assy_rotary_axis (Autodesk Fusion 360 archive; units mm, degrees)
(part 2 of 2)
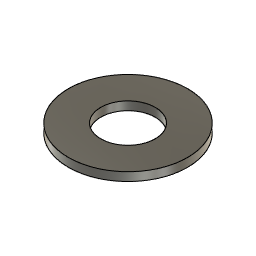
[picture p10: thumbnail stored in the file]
sketch "Sketch1" plane through (0, 0, 0) normal (0, 1, 0) x axis (1, 0, 0)
  line L1 (3.5, 0) -> (1.6, 0)
  line L2 (3.5, -0.5) -> (3.5, 0)
  line L3 (1.6, -0.5) -> (3.5, -0.5)
  line L4 (1.6, 0) -> (1.6, -0.5)
  point P1 (0, 0)
  point P2 (1.6, 0)
  point P5 (1.6, -0.5)
  horizontal L1
  vertical L2
  horizontal L3
  vertical L4
  coincident P1 L1
  dimension "d1" distance P2 P5 = 0.5
  dimension "d2" distance P1 L4 = 1.6 (= "( 3.2 / 2 ) * 1 mm")
  dimension "d3" distance P1 L2 = 3.5 (= "( 7 / 2 ) * 1 mm")
revolve "Revolve1" sketch "Sketch1" AlongAngle 360

design "PP_TRNS_GT2-Pulley-20T-6mm"
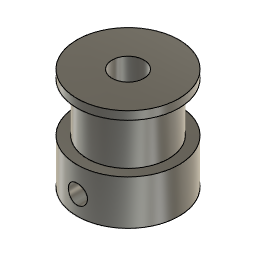
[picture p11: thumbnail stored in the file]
sketch "Sketch1" plane through (0, 0, 0) normal (0, 1, 0) x axis (1, 0, 0)
  line L1 (8, 0) -> (0, 0)
  line L2 (8, -7) -> (8, 0)
  line L3 (6.3662, -7) -> (8, -7)
  line L4 (6.3662, -14.7) -> (6.3662, -7)
  line L5 (8, -14.7) -> (6.3662, -14.7)
  line L6 (8, -16) -> (8, -14.7)
  line L7 (2.5, -16) -> (8, -16)
  line L8 (2.5, 0) -> (2.5, -16)
  line L9 (0, -3) -> (0, 0)
  circle C1 centre (0, -3) radius 1.5
  point P1 (0, 0)
  point P2 (0, 0)
  point P10 (2.5, 0)
  point P4 (8, -7)
  point P12 (0, 0)
  point P11 (0, -3)
  point P13 (0, -3)
  point P3 (8, 0)
  point P7 (8, -14.7)
  point P8 (8, -16)
  coincident P1 P2
  horizontal L1
  perpendicular L1 L2
  perpendicular L2 L3
  perpendicular L3 L4
  perpendicular L4 L5
  perpendicular L5 L6
  perpendicular L4 L7
  coincident L1 P10
  perpendicular L1 L8
  coincident P4 L6
  coincident P1 P12
  coincident P11 P13
  vertical L9
  dimension "d1" distance P1 L8 = 2.5 (= "( 5 / 2 ) * 1 mm")
  dimension "d2" distance P1 L2 = 8 (= "( 16 / 2 ) * 1 mm")
  dimension "d3" distance P3 P4 = 7
  dimension "d4" distance P1 L4 = 6.3662 (= "( 20 * 2 / PI ) * 1 mm / 2")
  dimension "d5" distance P7 P8 = 1.3
  dimension "d6" distance P3 L7 = 16
  dimension "d8" diameter C1 = 3
  dimension "d9" distance P12 P13 = 3
revolve "Revolve1" sketch "Sketch1" AlongAngle 360
extrude "Extrude1" cut sketch "Sketch1" profile of C1 against normal blind 17

design "PP_BRNG_6808-40x52x7"
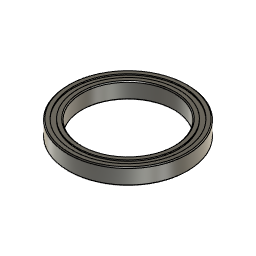
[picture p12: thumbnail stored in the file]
sketch "Sketch1" plane through (0, 0, 0) normal (0, 1, 0) x axis (1, 0, 0)
  line L1 (22, -3.5) -> (20, -3.5)
  line L2 (20, 3.5) -> (22, 3.5)
  line L3 (20, -3.5) -> (20, 3.5)
  line L4 (26, -3.5) -> (24, -3.5)
  line L5 (26, 3.5) -> (26, -3.5)
  line L6 (24, 3.5) -> (26, 3.5)
  line L7 (24, -3) -> (22, -3)
  line L8 (24, 3) -> (22, 3)
  line L9 (22, -3) -> (22, -3.5)
  line L10 (22, 3.5) -> (22, 3)
  line L11 (24, 3) -> (24, 3.5)
  line L12 (24, -3.5) -> (24, -3)
  line L13 (0, 0) -> (26, 0)
  point P11 (24, -3)
  point P12 (22, 3)
  point P14 (26, 0)
  point P1 (0, 0)
  point P15 (0, 0)
  point P16 (20, 0)
  point P6 (24, -3.5)
  point P2 (20, -3.5)
  point P3 (22, -3.5)
  point P10 (22, -3)
  point P7 (26, -3.5)
  point P8 (26, 3.5)
  horizontal L1
  vertical L9
  horizontal L2
  vertical L3
  horizontal L4
  vertical L5
  horizontal L6
  vertical L11
  coincident P11 L11
  perpendicular L7 L11
  coincident P12 L9
  perpendicular L8 L9
  collinear L9 L10
  collinear L11 L12
  midpoint L5 P14
  coincident P1 P15
  horizontal L13
  midpoint L3 P16
  coincident L13 P16
  equal L1 L4
  equal L9 L10
  coincident L1 P6
  dimension "d1" distance P1 L3 = 20 (= "( 40 / 2 ) * 1 mm")
  dimension "d3" distance P2 P3 = 2
  dimension "d4" distance P3 P10 = 0.5
  dimension "d5" distance P7 P8 = 7
  dimension "d8" distance P1 L5 = 26 (= "( 52 / 2 ) * 1 mm")
revolve "Revolve1" sketch "Sketch1" AlongAngle 360
chamfer "Chamfer1" distance 0.4

design "PP_ACTU_N17-Stepper"
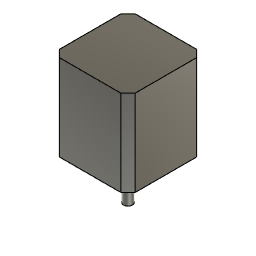
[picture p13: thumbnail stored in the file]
description: Nema 17 Stepper, 48mm Length Preferred, 5mm Shaft
sketch "Sketch1" plane through (0, 0, 0) normal (0, 0, 1) x axis (1, 0, 0)
  line L1 (-21.15, 21.15) -> (21.15, 21.15)
  line L2 (-21.15, -21.15) -> (-21.15, 21.15)
  line L3 (21.15, -21.15) -> (-21.15, -21.15)
  line L4 (21.15, 21.15) -> (21.15, -21.15)
  line L5 (-21.15, -21.15) -> (21.15, 21.15)
  line L6 (21.15, -21.15) -> (-21.15, 21.15)
  line L7 (15.5, 15.5) -> (-15.5, 15.5)
  line L8 (15.5, -15.5) -> (15.5, 15.5)
  line L9 (-15.5, -15.5) -> (15.5, -15.5)
  line L10 (-15.5, 15.5) -> (-15.5, -15.5)
  circle C1 centre (0, 0) radius 11
  circle C2 centre (-15.5, 15.5) radius 1.5
  circle C3 centre (-15.5, -15.5) radius 1.5
  circle C4 centre (15.5, -15.5) radius 1.5
  circle C5 centre (15.5, 15.5) radius 1.5
  circle C6 centre (0, 0) radius 2.5
  point P6 (0, 0)
  point P1 (0, 0)
  point P7 (0, 0)
  point P10 (15.5, -15.5)
  point P8 (-15.5, 15.5)
  point P9 (15.5, 15.5)
  point P12 (-15.5, 15.5)
  point P11 (-15.5, -15.5)
  point P13 (-15.5, -15.5)
  point P14 (15.5, -15.5)
  point P15 (15.5, 15.5)
  point P2 (21.15, 21.15)
  point P3 (-21.15, 21.15)
  perpendicular L1 L2
  parallel L1 L3
  parallel L2 L4
  horizontal L1
  coincident L5 P6
  coincident L6 P6
  coincident P1 P6
  equal L1 L2
  coincident P6 P7
  horizontal L7
  vertical L8
  horizontal L9
  vertical L10
  coincident L6 P10
  coincident L6 P8
  coincident L5 P9
  coincident P8 P12
  coincident P11 P13
  coincident P10 P14
  coincident P9 P15
  equal C2 C5
  equal C2 C3
  equal C2 C4
  concentric C1 C6
  dimension "d1" distance P2 P3 = 42.3
  dimension "d2" diameter C1 = 22
  dimension "d3" distance P8 P9 = 31
  dimension "d4" diameter C2 = 3
  dimension "d5" diameter C6 = 5
  dimension "d19" alignAngle = 0
  dimension "d20" alignOffsetX = 0
  dimension "d21" alignOffsetY = 0
  dimension "d22" alignOffsetZ = 0
  dimension "d23" alignAngle = 180
  dimension "d24" alignOffsetX = 0
  dimension "d25" alignOffsetY = 0
  dimension "d26" alignOffsetZ = 0
extrude "Extrude1" new body sketch "Sketch1" profile of L1 L2 L3 L4 C1 C2 C3 C4 C5 C6 along normal blind 48
extrude "Extrude2" cut sketch "Sketch1" profile of C2 C3 C4 C5 along normal blind 5
extrude "Extrude3" add sketch "Sketch1" profile of C1 C6 against normal blind 2
extrude "Extrude4" add sketch "Sketch1" profile of C6 against normal blind 24
chamfer "Chamfer1" distance 4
